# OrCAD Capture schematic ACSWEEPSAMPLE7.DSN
size A
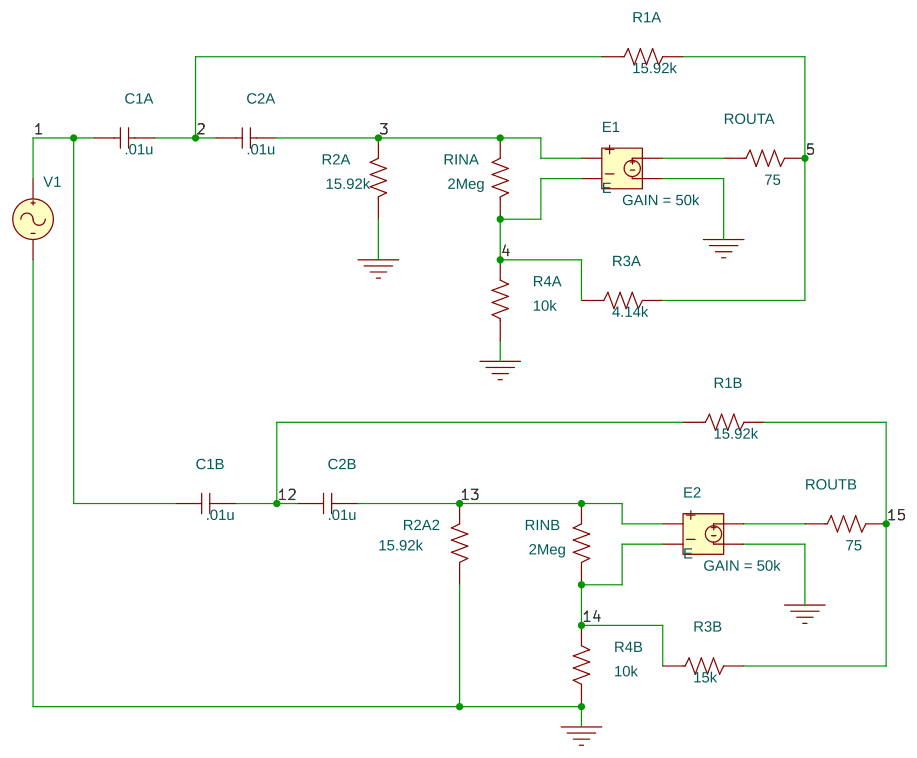
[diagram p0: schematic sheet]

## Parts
C1A  .01u  [RAD/CK05]
C1B  .01u  [RAD/CK05]
C2A  .01u  [RAD/CK05]
C2B  .01u  [RAD/CK05]
E1  E
E2  E
R1A  15.92k  [AX/RC05]
R1B  15.92k  [AX/RC05]
R2A  15.92k  [AX/RC05]
R2A2  15.92k  [AX/RC05]
R3A  4.14k  [AX/RC05]
R3B  15k  [AX/RC05]
R4A  10k  [AX/RC05]
R4B  10k  [AX/RC05]
RINA  2Meg  [AX/RC05]
RINB  2Meg  [AX/RC05]
ROUTA  75  [AX/RC05]
ROUTB  75  [AX/RC05]
V1  VAC

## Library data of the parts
C1A C1B C2A C2B = C
E1 E2 = E: GAIN: 50k
R1A R1B R2A R2A2 R3A R3B R4A R4B RINA RINB ROUTA ROUTB = R
V1 = VAC

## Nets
0: E1.4 E2.4 R2A.1 R2A2.1 R4A.1 R4B.1 V1.2(-)
1: C1A.1 C1B.1 V1.1(+)
2: C1A.2 C2A.1 R1A.1
3: C2A.2 E1.1 R2A.2 RINA.2
4: E1.2 R3A.1 R4A.2 RINA.1
5: R1A.2 R3A.2 ROUTA.2
12: C1B.2 C2B.1 R1B.1
13: C2B.2 E2.1 R2A2.2 RINB.2
14: E2.2 R3B.1 R4B.2 RINB.1
15: R1B.2 R3B.2 ROUTB.2
N17184: E1.3 ROUTA.1
N17494: E2.3 ROUTB.1
